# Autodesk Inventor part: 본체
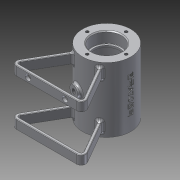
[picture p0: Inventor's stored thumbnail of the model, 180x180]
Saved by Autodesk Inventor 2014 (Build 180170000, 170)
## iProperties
Created: 2016-03
Part Number: 본체
Material: 알루미늄 6061
Document SubType Name: Modeling
Designer: SEC
Density: 2.71 g/cm^3
Appearance: 알루미늄 - 평지
Mass: 211.604 g
Surface Area: 327.768 cm^2
Volume: 78.0825 cm^3
Author: SEC
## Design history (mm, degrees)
sketch "스케치1"
  geometry: C1 r 26 at (0, 0); 1 further point
  constraints: 1 centre point, 1 coincident
  dimensions: "d0" = 52 diameter of C1
extrude "돌출1" new body sketch "스케치1" stored distance "d1" = 70; taper "d2" = 0 deg
sketch "스케치2"
  geometry: C1 r 26 at (0, 0) reference; C2 r 16 at (0, 0)
  constraints: 1 centre point, 1 coincident
  dimensions: "d3" = 32 diameter of C2
extrude "돌출2" cut sketch "스케치2" distance "d4" = 12; taper "d5" = 0 deg
sketch "스케치4"
  geometry: C1 r 16 at (0, 0) reference; C2 r 14 at (0, 0)
  constraints: 1 centre point, 1 coincident
  dimensions: "d9" = 28 diameter of C2
extrude "돌출4" cut sketch "스케치4" distance "d10" = 2; taper "d11" = 0 deg
sketch "스케치5"
  geometry: C1 r 14 at (0, 0) reference; C2 r 21 at (0, 0)
  constraints: 1 centre point, 1 coincident
  dimensions: "d12" = 42 diameter of C2
extrude "돌출5" cut sketch "스케치5" distance "d13" = 42; taper "d14" = 0 deg
sketch "스케치6"
  geometry: C1 r 26 at (0, 0) reference; C2 r 16 at (0, 0)
  constraints: 1 centre point, 1 coincident
  dimensions: "d15" = 32 diameter of C2
extrude "돌출6" cut sketch "스케치6" distance "d16" = 12; taper "d17" = 0 deg
sketch "스케치7"
  geometry: C1 r 16 at (0, 0) reference; C2 r 14 at (0, 0)
  constraints: 1 centre point, 1 coincident
  dimensions: "d18" = 28 diameter of C2
extrude "돌출7" cut sketch "스케치7" distance "d19" = 2; taper "d20" = 0 deg
node "작업 평면1"
sketch "스케치8"
  geometry: C1 r 5 at (0, 0); 1 further point
  constraints: 1 centre point, 1 coincident
  dimensions: "d22" = 10 diameter of C1
extrude "돌출8" join sketch "스케치8" stored distance "d23" = 10 (= d22); taper "d24" = 0 deg
sketch "스케치10"
  geometry: L1 (0, 0)-(21, 0); C1 r 26 at (0, 0) reference; 1 further point
  constraints: 2 end point, 1 coincident, 1 horizontal
  dimensions: "d25" = 21 distance of L1.start L1.end
hole "구멍1" sketch "스케치10" at (21, 0) diameter "d26" = 3.242; stored, may be unused: countersink angle "d30" = 90 deg, drill point angle "d32" = 118 deg; dims "d27" = 8, "d28" = 4, "d29" = 2, "d31" = 10
hole "구멍2" diameter "d38" = 5.188; stored, may be unused: countersink angle "d42" = 90 deg, drill point angle "d44" = 118 deg; dims "d36" = 10, "d37" = 10, "d39" = 8, "d40" = 4, "d41" = 2, "d43" = 30
node "작업 평면3"
  node "작업 평면2"
sketch "스케치12"
  geometry: C1 r 6 at (0, -21); 1 further point
  constraints: 1 centre point, 1 coincident
  dimensions: "d49" = 12 diameter of C1
extrude "돌출9" join sketch "스케치12" stored distance "d50" = 12 (= d49); taper "d51" = 0 deg
hole "구멍3" diameter "d54" = 5.188; stored, may be unused: countersink angle "d58" = 90 deg, drill point angle "d60" = 118 deg; dims "d52" = 10, "d53" = 10, "d55" = 8, "d56" = 4, "d57" = 2, "d59" = 30
node "작업 평면4"
sketch "스케치13"
  geometry: L1 (-15.629, -20.778)-(-36.83, -57.5); L2 (-32.5, -65)-(32.5, -65); L3 (36.83, -57.5)-(15.629, -20.778); L4 (0, 0)-(0, -65); L5 (13.126, -22.443)-(34.232, -59); L6 (32.5, -62)-(-32.5, -62); L7 (-34.232, -59)-(-13.126, -22.443); C1 r 16 at (0, 0) reference; A1 r 26 centre (0, 0) between (-15.629, -20.778) and (15.629, -20.778) reference; A2 r 26 centre (0, 0) between (-15.629, -20.778) and (-13.126, -22.443); A3 r 26 centre (0, 0) between (13.126, -22.443) and (15.629, -20.778); A4 r 5 centre (-32.5, -60) between (-36.83, -57.5) and (-32.5, -65); A5 r 5 centre (32.5, -60) between (32.5, -65) and (36.83, -57.5); A6 r 2 centre (32.5, -60) between (32.5, -62) and (34.232, -59); A7 r 2 centre (-32.5, -60) between (-34.232, -59) and (-32.5, -62); 4 further points
  constraints: 16 point on circle, 14 end point, 6 centre point, 4 point on line, 4 tangent, 2 midpoint, 1 coincident, 1 equal radius, 1 horizontal, 1 perpendicular, 1 vertical alignment, 4 other
  dimensions: "d62" = 65 distance from line of L2 point (0, 0); "d63" = 30 deg angle of L4 L3; "d64" = 30 deg angle of L4 L1; "d70" = 5 radius of A4; "d71" = 65 distance of L2.start L2.end; "d72" = 3 distance between parallel lines of L2 L6
extrude "돌출10" join sketch "스케치13" distance "d68" = 10; taper "d69" = 0 deg
sketch "스케치14"
  geometry: L1 (65, 0)-(65, 10) reference; L2 (0, 0)-(0, 10) reference; C1 r 3 at (12.5, 5); C2 r 3 at (52.5, 5); 3 further points
  constraints: 2 centre point, 2 horizontal alignment, 2 midpoint
  dimensions: "d73" = 6 diameter of C1; "d74" = 6 diameter of C2; "d75" = 20 horizontal distance of C1.centre point (32.5, 30); "d76" = 20 horizontal distance of C2.centre point (32.5, 30)
extrude "돌출11" cut sketch "스케치14" distance "d77" = 10; taper "d78" = 0 deg
node "작업 평면5"
fillet "모깎기1" dims "d80" = 2, "d81" = 0.3, "d82" = 3, "d83" = 0.5
fillet "모깎기2" dims "d84" = 3
chamfer "모따기1" distance "d85" = 1; stored, may be unused: second distance "d86" = 2, angle "d87" = 45 deg
chamfer "모따기2" distance "d88" = 1; stored, may be unused: second distance "d89" = 2, angle "d90" = 45 deg
node "작업 평면7"
sketch "스케치18"
  geometry: 2 further points
  constraints: 1 coincident, 1 other
feature "엠보싱2" sketch "스케치18" dims "d2" = 0, "d95" = 0.5, "d96" = 0
node "솔리드1"
pattern_circular "원형 패턴1" dims angle "d34" = 360 deg
mirror "대칭1"
mirror "대칭2"
node "작업축2"
other parameters: "d21" = 29, "d47" = 15 deg, "d48" = -29, "d79" = -26, "d94" = 26
